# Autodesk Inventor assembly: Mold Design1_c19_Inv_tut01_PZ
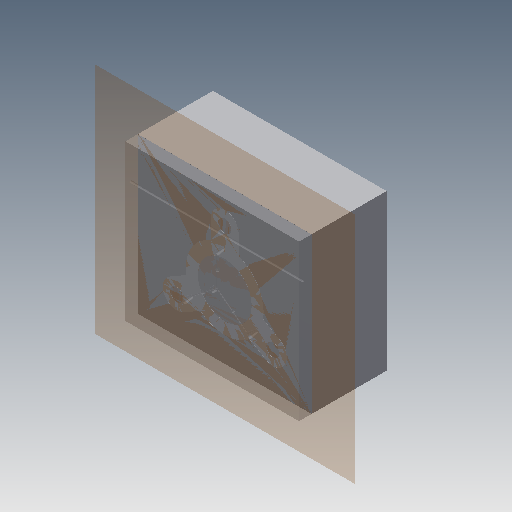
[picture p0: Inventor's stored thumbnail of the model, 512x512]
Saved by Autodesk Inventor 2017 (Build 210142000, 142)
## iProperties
Created: 2016-07
Part Number: Mold Design1_c19_Inv_tut01_PZ
Document SubType Name: Assembly
Designer: Sandeep
Author: Sandeep
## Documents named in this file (7)
- C:\Inventor_2017\c19\Mold Design1_c19_Inv_tut01_PZ.iam
- C:\Inventor_2017\c19\Mold Design1_c19_Inv_tut01_MP.ipt
- C:\Inventor_2017\c19\Mold Design1_c19_Inv_tut01_WP.ipt
- C:\Inventor_2017\c19\Mold Design1_c19_Inv_tut01_CR_Base.ipt
- C:\Inventor_2017\c19\Mold Design1_c19_Inv_tut01_CR_1.ipt
- C:\Inventor_2017\c19\Mold Design1_c19_Inv_tut01_CV_Base.ipt
- C:\Inventor_2017\c19\Mold Design1_c19_Inv_tut01_CV_1.ipt
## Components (6 placed, 6 different names)
1. Mold Design1_c19_Inv_tut01_MP:1 — Flush:1, Flush:2, Flush:3, Flush:4, Flush:5, Flush:6
2. Mold Design1_c19_Inv_tut01_WP:1 — Flush:4, Flush:5, Flush:6
3. Mold Design1_c19_Inv_tut01_CR_Base:1 — Flush:7, Flush:8, Flush:9, Flush:13, Flush:14, Flush:15
4. Mold Design1_c19_Inv_tut01_CR_1:1 — Flush:13, Flush:14, Flush:15
5. Mold Design1_c19_Inv_tut01_CV_Base:1 — Flush:10, Flush:11, Flush:12, Flush:16, Flush:17, Flush:18
6. Mold Design1_c19_Inv_tut01_CV_1:1 — Flush:16, Flush:17, Flush:18
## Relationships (18: Flush 18)
- Flush:1: Mold Design1_c19_Inv_tut01_MP:1
- Flush:2: Mold Design1_c19_Inv_tut01_MP:1
- Flush:3: Mold Design1_c19_Inv_tut01_MP:1
- Flush:4: Mold Design1_c19_Inv_tut01_MP:1 ↔ Mold Design1_c19_Inv_tut01_WP:1
- Flush:5: Mold Design1_c19_Inv_tut01_MP:1 ↔ Mold Design1_c19_Inv_tut01_WP:1
- Flush:6: Mold Design1_c19_Inv_tut01_MP:1 ↔ Mold Design1_c19_Inv_tut01_WP:1
- Flush:7: Mold Design1_c19_Inv_tut01_CR_Base:1
- Flush:8: Mold Design1_c19_Inv_tut01_CR_Base:1
- Flush:9: Mold Design1_c19_Inv_tut01_CR_Base:1
- Flush:10: Mold Design1_c19_Inv_tut01_CV_Base:1
- Flush:11: Mold Design1_c19_Inv_tut01_CV_Base:1
- Flush:12: Mold Design1_c19_Inv_tut01_CV_Base:1
- Flush:13: Mold Design1_c19_Inv_tut01_CR_Base:1 ↔ Mold Design1_c19_Inv_tut01_CR_1:1
- Flush:14: Mold Design1_c19_Inv_tut01_CR_Base:1 ↔ Mold Design1_c19_Inv_tut01_CR_1:1
- Flush:15: Mold Design1_c19_Inv_tut01_CR_Base:1 ↔ Mold Design1_c19_Inv_tut01_CR_1:1
- Flush:16: Mold Design1_c19_Inv_tut01_CV_Base:1 ↔ Mold Design1_c19_Inv_tut01_CV_1:1
- Flush:17: Mold Design1_c19_Inv_tut01_CV_Base:1 ↔ Mold Design1_c19_Inv_tut01_CV_1:1
- Flush:18: Mold Design1_c19_Inv_tut01_CV_Base:1 ↔ Mold Design1_c19_Inv_tut01_CV_1:1
